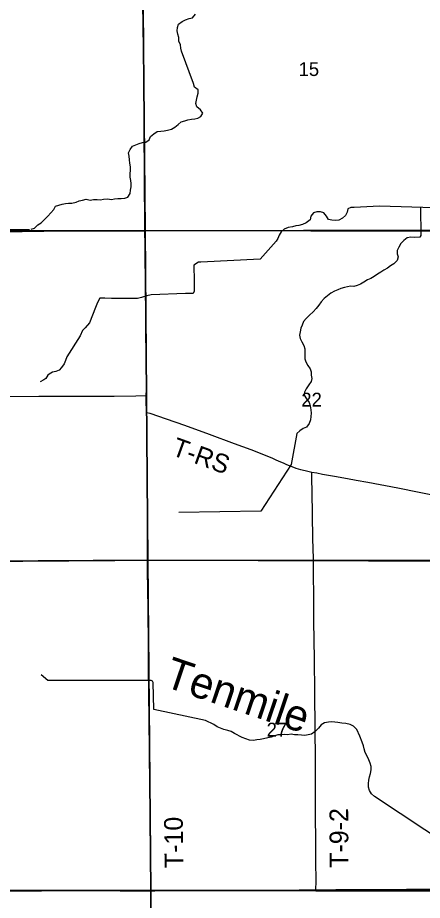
# Model space of a CAD drawing. Extents: x 0 to 34, y 0 to 22.
# Drawn here: x 4.098 to 5.327, y 16.618 to 19.3 of the extents above; entities that cross this region are included whole.
import ezdxf

# ---------------------------------------------------------------- set-up
doc = ezdxf.new("R2010")
doc.units = 0
for name, color, linetype in [('Default', 7, 'Continuous'), ('GM_X_County_Road', 7, 'Continuous'), ('GM_X_Minor_River', 7, 'Continuous'), ('GM_X_Minor_River_Text', 7, 'Continuous'), ('GM_X_Section', 7, 'Continuous'), ('GM_X_Section_Text', 7, 'Continuous'), ('GM_X_Township_Road', 7, 'Continuous'), ('GM_X_Township_Road_Text', 7, 'Continuous'), ('GM_X_US_Route', 7, 'Continuous')]:
    doc.layers.add(name, color=color, linetype=linetype)

msp = doc.modelspace()

# ---------------------------------------------------------------- linework, layer by layer
at = {"layer": 'Default'}
for points in [[(4.0639, 16.648), (4.2411, 16.648), (4.3715, 16.6478), (4.4088, 16.6475), (4.5018, 16.6475), (4.5145, 16.6475), (4.7352, 16.6481), (4.7881, 16.6479), (4.9528, 16.649), (5.0033, 16.6491), (5.0648, 16.6493), (5.2793, 16.6503), (5.5058, 16.651)], [(5.5058, 16.651), (5.2793, 16.6503), (5.0648, 16.6493), (5.0033, 16.6491), (4.9528, 16.649), (4.7881, 16.6479), (4.7352, 16.6481), (4.5145, 16.6475), (4.5018, 16.6475), (4.4088, 16.6475), (4.3715, 16.6478), (4.2411, 16.648), (4.0639, 16.648)]]:
    msp.add_lwpolyline(points, dxfattribs=at)
at = {"layer": 'GM_X_County_Road'}
for points in [[(3.735, 18.6489), (3.7913, 18.6492), (3.8472, 18.6494), (3.8939, 18.65), (4.0026, 18.6497), (4.1114, 18.6505), (4.1767, 18.651), (4.3384, 18.6517), (4.4843, 18.6526)], [(4.4843, 18.6526), (4.5342, 18.653), (4.7114, 18.6535), (4.9663, 18.6544), (5.1249, 18.6544), (5.1746, 18.6543), (5.2305, 18.654), (5.3611, 18.6537), (5.4896, 18.6535)], [(3.7543, 16.6471), (3.8671, 16.6474), (3.9367, 16.6473), (4.0642, 16.6475), (4.2414, 16.6474), (4.3717, 16.6472), (4.409, 16.647), (4.5021, 16.6469)], [(4.5021, 16.6469), (4.5147, 16.6469), (4.7355, 16.6476), (4.7883, 16.6474), (4.9531, 16.6484), (5.0035, 16.6486)], [(5.0035, 16.6486), (5.065, 16.6487), (5.2795, 16.6497), (5.5061, 16.6504)]]:
    msp.add_lwpolyline(points, dxfattribs=at)
at = {"layer": 'GM_X_Minor_River'}
for points in [[(4.1391, 18.657), (4.1486, 18.6607), (4.1593, 18.6701), (4.1689, 18.6768), (4.1792, 18.6866), (4.1892, 18.6964), (4.1988, 18.7069), (4.2076, 18.7171), (4.2126, 18.7269), (4.2229, 18.7302), (4.2328, 18.7335), (4.2427, 18.7353), (4.2522, 18.736), (4.2624, 18.7363), (4.275, 18.7395), (4.2849, 18.7432), (4.2951, 18.7458), (4.3061, 18.748), (4.3179, 18.7456), (4.3277, 18.7478), (4.3387, 18.7476), (4.3493, 18.7468), (4.3588, 18.7486), (4.3706, 18.7489), (4.3823, 18.7476), (4.3922, 18.7498), (4.4021, 18.7501), (4.4123, 18.7503), (4.4233, 18.7514), (4.4328, 18.7547), (4.4394, 18.7656), (4.4406, 18.7759), (4.4426, 18.7857), (4.442, 18.7956), (4.4417, 18.8055), (4.4399, 18.815), (4.4403, 18.8468), (4.4385, 18.8579), (4.4378, 18.8681), (4.4361, 18.8788), (4.4346, 18.889), (4.4397, 18.8988), (4.447, 18.9094), (4.4569, 18.9139), (4.4664, 18.9176), (4.4774, 18.9201), (4.4873, 18.9219), (4.4973, 18.929), (4.5015, 18.9388), (4.5111, 18.9471), (4.521, 18.9542), (4.5324, 18.9545), (4.5427, 18.9559), (4.5533, 18.9584), (4.5647, 18.9606), (4.5754, 18.967), (4.5849, 18.9752), (4.5945, 18.9831), (4.6052, 18.9864), (4.615, 18.989), (4.6257, 18.9915), (4.6355, 18.9926), (4.645, 18.9947), (4.6546, 18.9992), (4.6604, 19.0094), (4.6529, 19.0197), (4.6416, 19.0289), (4.6387, 19.0388), (4.6411, 19.0487), (4.6435, 19.0593), (4.6459, 19.0706), (4.646, 19.0809), (4.6347, 19.0886), (4.6318, 19.1), (4.5953, 19.1979), (4.5931, 19.2074), (4.5925, 19.2173), (4.5877, 19.2283), (4.5878, 19.2397), (4.5841, 19.25), (4.5827, 19.2602), (4.5832, 19.2701), (4.5867, 19.2803), (4.5978, 19.2886), (4.6073, 19.293), (4.6184, 19.2978), (4.6286, 19.2996), (4.6382, 19.3109)], [(5.1198, 18.7229), (5.1103, 18.7226), (5.1004, 18.7193), (5.0984, 18.7087), (5.0941, 18.6988), (5.0842, 18.6902), (5.0739, 18.685), (5.064, 18.684), (5.0519, 18.6845), (5.0421, 18.6868), (5.0357, 18.6968), (5.0283, 18.7067), (5.0181, 18.7095), (5.0067, 18.7099), (4.9968, 18.707), (4.9887, 18.6965), (4.986, 18.6859), (4.9745, 18.6765), (4.9634, 18.6717), (4.9524, 18.6684), (4.9425, 18.6669), (4.9323, 18.6648), (4.9197, 18.6618), (4.9076, 18.6574), (4.898, 18.6488), (4.8922, 18.639), (4.8879, 18.6288), (4.8833, 18.6205)], [(5.617, 18.7373), (5.4924, 18.718), (5.1972, 18.7274), (5.1198, 18.7229)], [(5.3214, 18.7235), (5.3225, 18.6377)], [(3.8362, 18.6577), (4.1334, 18.6567)], [(4.8833, 18.6205), (4.8342, 18.5659), (4.6544, 18.5574), (4.6475, 18.5571), (4.633, 18.5474), (4.6328, 18.5292), (4.6338, 18.517), (4.6341, 18.4685), (4.6306, 18.462), (4.6241, 18.4613), (4.6075, 18.4615), (4.5028, 18.4576), (4.4899, 18.4551), (4.4735, 18.4499), (4.4617, 18.447), (4.4507, 18.4464), (4.3829, 18.4463), (4.362, 18.4476), (4.3469, 18.4478), (4.3403, 18.4345), (4.3337, 18.4194), (4.3154, 18.3729), (4.3027, 18.3571), (4.2943, 18.3492), (4.2873, 18.333), (4.2471, 18.2692), (4.2428, 18.2583), (4.2386, 18.2481), (4.2312, 18.2364), (4.224, 18.2292), (4.2137, 18.2252), (4.2038, 18.2226), (4.1935, 18.217), (4.1897, 18.2133), (4.1827, 18.2038), (4.177, 18.1993), (4.1663, 18.1937)], [(5.3225, 18.6377), (5.3193, 18.6331), (5.3027, 18.6319), (5.2921, 18.6327), (5.2811, 18.6313), (5.2711, 18.6231), (5.2615, 18.6133), (5.2561, 18.6027), (5.2503, 18.5925), (5.251, 18.5827), (5.2535, 18.5728), (5.2511, 18.5622), (5.2408, 18.5516), (5.2309, 18.5457), (5.2213, 18.5386), (5.2106, 18.5322), (5.2011, 18.5262), (5.1908, 18.5206), (5.1805, 18.5135), (5.1706, 18.5072), (5.1603, 18.5031), (5.1492, 18.496), (5.1389, 18.4904), (5.1294, 18.4863), (5.1195, 18.483), (5.1093, 18.4839), (5.0998, 18.4824), (5.0903, 18.4795), (5.08, 18.4773), (5.0705, 18.4729), (5.0602, 18.4688), (5.0495, 18.4632), (5.0392, 18.4546), (5.0293, 18.4467), (5.0201, 18.4366), (5.0127, 18.426), (5.0047, 18.4162), (4.9951, 18.4064), (4.9844, 18.3963), (4.974, 18.3862), (4.9663, 18.3764), (4.9624, 18.3658), (4.9585, 18.3559), (4.9561, 18.3453), (4.9541, 18.3355), (4.9559, 18.3245), (4.9611, 18.3146), (4.9674, 18.3039), (4.97, 18.294), (4.9699, 18.283), (4.9701, 18.2731), (4.9704, 18.2636), (4.973, 18.2541), (4.9789, 18.2434), (4.9864, 18.2331), (4.9893, 18.2232), (4.9896, 18.2137), (4.9914, 18.2038), (4.9894, 18.194), (4.9824, 18.1838), (4.974, 18.1725), (4.9689, 18.1619), (4.9685, 18.1524), (4.9755, 18.1414), (4.983, 18.1307), (4.9867, 18.1204), (4.9885, 18.1086), (4.9899, 18.0983), (4.9886, 18.0881), (4.9874, 18.0775), (4.9834, 18.0669), (4.9754, 18.056), (4.9655, 18.0519), (4.9555, 18.044), (4.946, 18.0361)], [(4.946, 18.0361), (4.929, 17.9418), (4.8361, 17.8008), (4.5877, 17.7964)], [(4.6687, 17.1642), (4.5113, 17.1972), (4.5096, 17.2792), (4.507, 17.2838), (4.5028, 17.2854), (4.4937, 17.2862), (4.1889, 17.2862), (4.169, 17.3027)], [(5.1824, 16.9329), (5.1727, 16.941), (5.1664, 16.9517), (5.1634, 16.9616), (5.1632, 16.9726), (5.1648, 16.9824), (5.1672, 16.9934), (5.1696, 17.0033), (5.172, 17.0146), (5.1713, 17.0241), (5.1692, 17.0348), (5.1647, 17.0451), (5.1596, 17.0561), (5.154, 17.0668), (5.1507, 17.0778), (5.1485, 17.0877), (5.1441, 17.098), (5.1375, 17.117), (5.1286, 17.1369), (5.1185, 17.1468), (5.1079, 17.1523), (5.0947, 17.1554), (5.0826, 17.1559), (5.0709, 17.1583), (5.061, 17.1595), (5.0512, 17.1604), (5.0417, 17.159), (5.0303, 17.1572), (5.02, 17.1512), (5.0119, 17.1411), (5.0012, 17.1309), (4.9905, 17.1227), (4.9802, 17.1205), (4.9699, 17.1187), (4.9597, 17.1196), (4.9487, 17.1208), (4.9385, 17.1209), (4.9287, 17.1222), (4.918, 17.1207), (4.9082, 17.1212), (4.8987, 17.1202), (4.8885, 17.1203), (4.8786, 17.1173), (4.8679, 17.114), (4.8573, 17.1111), (4.8451, 17.1086), (4.8341, 17.106), (4.8242, 17.105), (4.8143, 17.1036), (4.8018, 17.1044), (4.7909, 17.1083), (4.7803, 17.113), (4.757, 17.125), (4.7468, 17.1304), (4.7362, 17.1335), (4.7245, 17.1367), (4.7139, 17.141), (4.7041, 17.1452), (4.6939, 17.1522), (4.6687, 17.1642)], [(5.4128, 16.7804), (5.1824, 16.9329)]]:
    msp.add_lwpolyline(points, dxfattribs=at)
at = {"layer": 'GM_X_Section'}
for points in [[(3.4763, 19.6515), (4.4763, 19.663), (4.4846, 18.6535), (3.4848, 18.6515)], [(4.4763, 19.663), (5.485, 19.653), (5.4908, 18.6512), (4.4846, 18.6535)], [(3.4848, 18.6515), (4.4846, 18.6535), (4.4933, 17.6509), (3.4923, 17.6455)], [(4.4846, 18.6535), (5.4908, 18.6512), (5.4987, 17.6483), (4.4933, 17.6509)], [(3.4923, 17.6455), (4.4933, 17.6509), (4.5021, 16.6472), (3.5053, 16.6448)], [(4.4933, 17.6509), (5.4987, 17.6483), (5.5052, 16.6454), (4.5021, 16.6472)], [(3.5053, 16.6448), (4.5021, 16.6472), (4.5104, 15.6416), (3.5041, 15.6366)], [(4.5021, 16.6472), (5.5052, 16.6454), (5.5125, 15.6443), (4.5104, 15.6416)]]:
    msp.add_lwpolyline(points, close=True, dxfattribs=at)
at = {"layer": 'GM_X_Township_Road'}
for points in [[(4.4843, 18.6526), (4.4841, 18.6577), (4.4843, 18.6637), (4.484, 18.6978), (4.4833, 18.7818), (4.4831, 18.7911), (4.4826, 18.8563), (4.4825, 18.9216), (4.482, 18.9745), (4.4816, 19.018), (4.4806, 19.1145), (4.4797, 19.2047), (4.478, 19.3446), (4.4772, 19.4162), (4.4766, 19.4784), (4.475, 19.609), (4.4739, 19.6545)], [(4.4884, 18.1515), (4.4886, 18.1696), (4.488, 18.2847), (4.4875, 18.3375), (4.4871, 18.3904), (4.4848, 18.5864), (4.4849, 18.6206), (4.4844, 18.6392), (4.4845, 18.6485), (4.4843, 18.6526)], [(3.988, 18.1488), (4.1616, 18.1495), (4.2745, 18.1496), (4.3289, 18.1502), (4.3905, 18.1502), (4.4567, 18.1511), (4.4884, 18.1515)], [(4.4899, 18.1006), (4.4899, 18.104), (4.4897, 18.1102), (4.4893, 18.1131), (4.4888, 18.1159), (4.4884, 18.1219), (4.4884, 18.1375), (4.4884, 18.1515)], [(4.4923, 17.6513), (4.4924, 17.6717), (4.4922, 17.6872), (4.492, 17.7774), (4.4912, 17.908), (4.4898, 18.0884), (4.4899, 18.1006)], [(4.4899, 18.1006), (4.4992, 18.0978), (4.5489, 18.0812), (4.6042, 18.0617), (4.68, 18.0341), (4.7557, 18.0062), (4.8058, 17.9875), (4.8346, 17.9763), (4.8617, 17.9654), (4.8697, 17.9619), (4.8824, 17.9565), (4.896, 17.9507), (4.9043, 17.947), (4.915, 17.9424), (4.9305, 17.9358), (4.9429, 17.9312), (4.957, 17.9271), (4.9712, 17.9236), (4.9795, 17.9217), (4.991, 17.9191)], [(4.991, 17.9191), (5.0068, 17.9165), (5.0238, 17.9131), (5.0601, 17.9065), (5.1001, 17.8993), (5.1258, 17.8944), (5.1612, 17.8881), (5.2531, 17.8708), (5.382, 17.8453), (5.4122, 17.8389), (5.4184, 17.8375), (5.4244, 17.8362), (5.4291, 17.8352), (5.4345, 17.8343), (5.4611, 17.8299), (5.4729, 17.8282), (5.475, 17.8281), (5.4773, 17.8279), (5.4799, 17.8277), (5.4869, 17.8279), (5.4917, 17.828), (5.4981, 17.828)], [(4.9964, 17.6517), (4.9963, 17.655), (4.9948, 17.717), (4.9925, 17.8598), (4.9919, 17.8971), (4.991, 17.9191)], [(4.5021, 16.6469), (4.5021, 16.6578), (4.5021, 16.6765), (4.5014, 16.7387), (4.4999, 16.888), (4.4998, 16.9191), (4.4991, 16.9595), (4.4981, 17.0746), (4.4972, 17.1617), (4.4964, 17.2519), (4.4955, 17.3172), (4.4955, 17.3296), (4.4953, 17.3514), (4.4949, 17.4012), (4.494, 17.4914), (4.4929, 17.5753), (4.4922, 17.6064), (4.492, 17.6313), (4.4923, 17.6468), (4.4923, 17.6513)], [(5.0035, 16.6486), (5.0037, 16.6552), (5.0042, 16.6708), (5.0039, 16.7423), (5.003, 16.9317), (5.0022, 17.0683), (5.0018, 17.118), (5.0006, 17.2701), (4.9999, 17.3291), (4.9995, 17.3509), (4.9979, 17.4656), (4.998, 17.4842), (4.9979, 17.5121), (4.9968, 17.6394), (4.9964, 17.6517)], [(3.7543, 16.6471), (3.8671, 16.6474), (3.9367, 16.6473), (4.0642, 16.6475), (4.2414, 16.6474), (4.3717, 16.6472), (4.409, 16.647), (4.5021, 16.6469)], [(4.5021, 16.6469), (4.5147, 16.6469), (4.7355, 16.6476), (4.7883, 16.6474), (4.9531, 16.6484), (5.0035, 16.6486)], [(4.5101, 15.6428), (4.5099, 15.7724), (4.5094, 15.9247), (4.5087, 16.077), (4.5082, 16.1111), (4.5063, 16.2914), (4.5055, 16.3659), (4.503, 16.5586), (4.5024, 16.6295), (4.5021, 16.6469)], [(5.0035, 16.6486), (5.065, 16.6487), (5.2795, 16.6497), (5.5061, 16.6504)]]:
    msp.add_lwpolyline(points, dxfattribs=at)
at = {"layer": 'GM_X_US_Route'}
for points in [[(3.9926, 17.6471), (4.1134, 17.6482), (4.3931, 17.6507), (4.4923, 17.6513), (4.5081, 17.6514), (4.5423, 17.6513), (4.5671, 17.6513), (4.738, 17.6516), (4.7816, 17.6517), (4.9525, 17.6517), (4.9964, 17.6517), (5.0334, 17.6517)], [(5.0334, 17.6517), (5.2384, 17.6517), (5.4056, 17.6521), (5.4994, 17.652)]]:
    msp.add_lwpolyline(points, dxfattribs=at)

# ---------------------------------------------------------------- texts
at = {"layer": 'GM_X_Minor_River_Text'}
msp.add_text('Tenmile', height=0.09477, rotation=341.3083, dxfattribs=at).set_placement((4.5379, 17.2693))
at = {"layer": 'GM_X_Section_Text'}
for s, p in [('15', (4.9513, 19.1226)), ('22', (4.9596, 18.1183)), ('27', (4.8542, 17.1155))]:
    msp.add_text(s, height=0.04186, rotation=0, dxfattribs=at).set_placement(p)
at = {"layer": 'GM_X_Township_Road_Text'}
for s, rotation, p in [('T-RS', 340.0716, (4.5625, 17.9719)), ('T-9-2', 90.3014, (5.1028, 16.7167)), ('T-10', 90.7083, (4.6011, 16.7158))]:
    msp.add_text(s, height=0.05682, rotation=rotation, dxfattribs=at).set_placement(p)

doc.saveas('drawing.dxf')
